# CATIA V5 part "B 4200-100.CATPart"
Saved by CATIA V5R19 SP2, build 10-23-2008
Part number: B 4200-100
Bounding box of the stored display mesh (mm): x -47.487 to 47.487, y -47.487 to 47.487, z 0 to 320
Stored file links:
  C:\Users\Bora\Desktop\3D Katı model\B serisi\B 4200\B 4200-100.CATPart
  C:\Program Files\Dassault Systemes\B19\intel_a\reffiles\standard\MetricThickPitch.txt
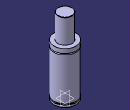
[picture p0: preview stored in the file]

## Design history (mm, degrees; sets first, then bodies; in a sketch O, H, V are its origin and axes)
Body1 (main body)
  Sketch1 on yz-plane, origin (0, 0, 0), H (0, 1, 0), V (0, 0, 1)
    point P1 (47.5, 198.5)
    point P2 (47.5, 193.5)
    point P3 (47.5, 198.5)
    point P6 (47.5, 193.5)
    point P9 (30, 319)
    point P11 (30, 319)
    arc A1 centre (47.5, 196) radius 2.5 from (47.5, 198.5) to (47.5, 193.5) ccw
    line L1 (47.5, 198.5) -> (47.5, 217)
    line L2 (47.5, 13) -> (47.5, 193.5)
    line L3 (43.5, 13) -> (43.5, 8)
    arc A2 centre (29, 319) radius 1 from (30, 319) to (29, 320) ccw
    line L4 (30, 319) -> (30, 217)
    line L5 (47.5, 0) -> (47.5, 8)
    line L6 (29, 320) -> (0, 320)
    point P15 (0, 320)
    line L7 (30, 217) -> (47.5, 217)
    line L8 (0, 0) -> (47.5, 0)
    line L9 (43.5, 8) -> (47.5, 8)
    line L10 (43.5, 13) -> (47.5, 13)
    coincidence: P15 V, P1 P3, P2 P6, P9 P11
    tangency: L6 A2
    horizontal: L7 H, L8 H, L9 H, L10 H
  Shaft1: profile Sketch1, axis Sketch1.V, angle 360
  Sketch2 on face of Shaft1 from Sketch1.L8, origin (0, 0, 0), H (1, 0, 0), V (0, -1, 0)
    point P1 (30, 0)
    distance P1 V = 30
  Hole1: placed by Sketch2, at (30, 0, 0) direction (0, 0, 1), diameter 6.647, depth 13, threaded "M8", thread diameter 8, thread depth 13, pitch 1.25
  CircPattern1: of Hole1, instances 4, angular step 90, axis from xy-plane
